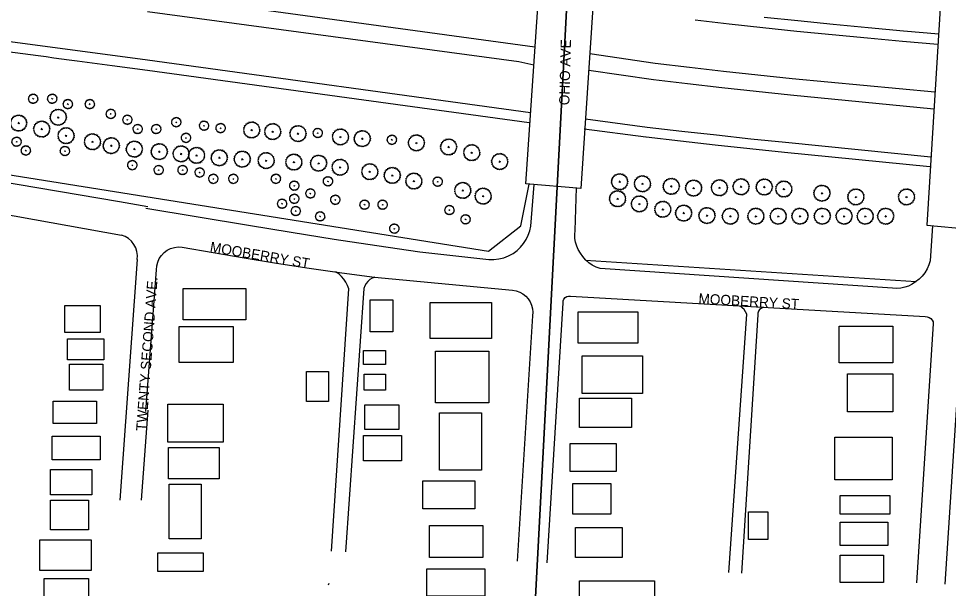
# Model space of a CAD drawing. Extents: x -9648 to 41057, y -12373 to 40276.
# Drawn here: x 11921 to 12833, y -5476 to -4917 of the extents above; entities that cross this region are included whole.
import ezdxf

# ---------------------------------------------------------------- set-up
doc = ezdxf.new("R2010")
doc.units = 0
for name, color, linetype in [('Default', 7, 'Continuous'), ('PM_X_Stop_Line', 7, 'Continuous'), ('SC_Scratch1', 7, 'Continuous'), ('SH_Data', 7, 'Continuous')]:
    doc.layers.add(name, color=color, linetype=linetype)

# ---------------------------------------------------------------- blocks, each defined once
blk = doc.blocks.new('15_PIN')
at = {"layer": 'Default'}
for p, q in [((-2.8, 0), (2.8, 0)), ((0, 2.8), (0, -2.8))]:
    blk.add_line(p, q, dxfattribs=at)
for centre, start, end in [((-25.5, 4.5), 275.99, 64.01), ((-25.9, -1.5), 289.3234, 77.3433), ((-23.8, 10.3), 262.6567, 50.6766), ((-20.8, 15.5), 249.3234, 37.3433), ((-16.7, 19.8), 235.99, 24.01), ((-11.6, 23.2), 222.6567, 10.6766), ((-6, 25.2), 209.3234, 357.3433), ((0, 25.9), 195.99, 344.01), ((6, 25.2), 182.6567, 330.6766), ((11.6, 23.2), 169.3234, 317.3433), ((16.7, 19.8), 155.99, 304.01), ((20.8, 15.5), 142.6567, 290.6766), ((23.8, 10.3), 129.3234, 277.3433), ((25.5, 4.5), 115.99, 264.01), ((25.9, -1.5), 102.6567, 250.6766), ((-24.8, -7.4), 302.6567, 90.6766), ((-22.4, -13), 315.99, 104.01), ((-18.8, -17.8), 329.3234, 117.3433), ((-14.2, -21.6), 342.6567, 130.6766), ((-8.9, -24.3), 355.99, 144.01), ((-3, -25.7), 9.3234, 157.3433), ((3, -25.7), 22.6567, 170.6766), ((8.9, -24.3), 35.99, 184.01), ((14.2, -21.6), 49.3234, 197.3433), ((18.8, -17.8), 62.6567, 210.6767), ((22.4, -13), 75.99, 224.01), ((24.8, -7.4), 89.3234, 237.3433)]:
    blk.add_arc(centre, 3.05, start, end, dxfattribs=at)

msp = doc.modelspace()

# ---------------------------------------------------------------- linework, layer by layer
at = {"layer": 'PM_X_Stop_Line'}
msp.add_arc((9361.23, -8468.95), 3904.03, 82.5, 82.5, dxfattribs=at)
at = {"layer": 'SC_Scratch1'}
for p, q in [((12492.94, -4255.51), (12411.7, -5793.36)), ((12411.7, -5793.36), (12492.94, -4255.51)), ((12492.94, -4255.51), (12411.7, -5793.36))]:
    msp.add_line(p, q, dxfattribs=at)
at = {"layer": 'SH_Data'}
for p, q in [((12418.48, -5079.16), (12435.28, -4831.86)), ((12488.68, -4838.26), (12472.68, -5083.66)), ((12826.88, -4875.06), (12811.88, -5119.86)), ((12427.58, -4944.96), (12047.69, -4893.08)), ((12047.7, -4910.08), (12411.88, -4959.26)), ((12584.68, -4918.26), (12617.98, -4922.06)), ((12617.98, -4922.06), (12651.18, -4925.76)), ((12685.52, -4919.32), (12652.22, -4915.82)), ((12719.98, -4922.81), (12685.48, -4919.31)), ((12754.53, -4926.11), (12719.93, -4922.81)), ((12651.18, -4925.76), (12684.48, -4929.26)), ((12684.48, -4929.26), (12718.98, -4932.76)), ((12718.98, -4932.76), (12753.58, -4936.06)), ((12789.1, -4929.3), (12754.5, -4926.1)), ((12823.64, -4932.3), (12789.04, -4929.3)), ((12753.58, -4936.06), (12788.18, -4939.26)), ((12788.18, -4939.26), (12822.78, -4942.26)), ((12481.28, -4951.36), (12545.48, -4960.86)), ((12481.28, -4951.36), (12545.48, -4960.86)), ((12423.18, -5009.46), (12047.73, -4957.68)), ((12411.88, -4959.26), (12426.38, -4962.46)), ((12421.85, -5019.37), (12047.73, -4967.88)), ((12480.28, -4967.66), (12543.68, -4976.86)), ((12545.48, -4960.86), (12578.98, -4964.86)), ((12545.48, -4960.86), (12578.98, -4964.86)), ((12578.98, -4964.86), (12612.58, -4968.66)), ((12578.98, -4964.86), (12612.58, -4968.66)), ((12612.58, -4968.66), (12646.08, -4972.36)), ((12612.58, -4968.66), (12646.08, -4972.36)), ((12543.68, -4976.86), (12577.28, -4980.86)), ((12646.08, -4972.36), (12679.68, -4975.86)), ((12679.68, -4975.86), (12819.88, -4989.06)), ((12577.28, -4980.86), (12610.88, -4984.66)), ((12610.88, -4984.66), (12644.48, -4988.36)), ((12644.48, -4988.36), (12678.08, -4991.86)), ((12678.08, -4991.86), (12818.88, -5005.56)), ((11514.42, -5006.69), (12381.93, -5145.2)), ((12477.08, -5015.56), (12537.68, -5023.46)), ((12537.68, -5023.46), (12571.58, -5027.46)), ((12536.38, -5033.38), (12475.78, -5025.48)), ((12570.4, -5037.39), (12536.5, -5033.39)), ((12571.58, -5027.46), (12605.48, -5031.26)), ((12605.48, -5031.26), (12639.38, -5034.96)), ((12604.36, -5041.2), (12570.46, -5037.4)), ((12638.29, -5044.9), (12604.39, -5041.2)), ((12639.38, -5034.96), (12673.28, -5038.46)), ((12673.28, -5038.46), (12815.98, -5052.66)), ((12672.25, -5048.41), (12638.35, -5044.91)), ((12814.99, -5062.61), (12672.29, -5048.41)), ((12472.68, -5083.66), (12418.48, -5079.16)), ((11785.61, -5087.23), (12022.03, -5129.49)), ((12413.71, -5120.39), (12421.77, -5079.44)), ((12423.48, -5120.66), (12426.68, -5079.86)), ((12466.88, -5125.06), (12468.28, -5083.26)), ((12046.08, -5103.06), (12146.68, -5119.66)), ((12146.68, -5119.66), (12188.58, -5126.66)), ((12381.93, -5145.2), (12413.71, -5120.39)), ((12422.48, -5125.26), (12423.48, -5120.66)), ((12811.88, -5119.86), (12864.68, -5124.66)), ((12817.48, -5120.36), (12815.08, -5154.66)), ((12188.58, -5126.66), (12230.58, -5133.46)), ((12230.58, -5133.46), (12272.58, -5139.86)), ((12416.38, -5137.76), (12418.88, -5133.86)), ((12418.88, -5133.86), (12420.88, -5129.66)), ((12420.88, -5129.66), (12422.48, -5125.26)), ((12466.58, -5128.86), (12466.88, -5125.06)), ((12466.78, -5132.76), (12466.58, -5128.86)), ((12467.48, -5136.56), (12466.78, -5132.76)), ((12066.98, -5144.36), (12070.28, -5142.66)), ((12070.28, -5142.66), (12073.98, -5141.56)), ((12073.98, -5141.56), (12077.68, -5141.06)), ((12077.68, -5141.06), (12081.48, -5141.26)), ((12081.48, -5141.26), (12142.28, -5151.66)), ((12272.58, -5139.86), (12314.68, -5146.06)), ((12410.08, -5144.66), (12413.48, -5141.36)), ((12413.48, -5141.36), (12416.38, -5137.76)), ((12468.58, -5140.26), (12467.48, -5136.56)), ((12470.08, -5143.76), (12468.58, -5140.26)), ((12059.18, -5152.56), (12061.28, -5149.36)), ((12061.28, -5149.36), (12063.88, -5146.66)), ((12063.88, -5146.66), (12066.98, -5144.36)), ((12142.28, -5151.66), (12174.18, -5156.96)), ((12314.68, -5146.06), (12382.48, -5153.46)), ((12392.28, -5152.86), (12397.08, -5151.66)), ((12397.08, -5151.66), (12401.68, -5149.86)), ((12401.68, -5149.86), (12406.08, -5147.56)), ((12406.08, -5147.56), (12410.08, -5144.66)), ((12472.08, -5147.06), (12470.08, -5143.76)), ((12474.38, -5150.56), (12472.08, -5147.06)), ((12477.08, -5153.86), (12474.38, -5150.56)), ((12037.45, -5153.49), (12020.35, -5389.45)), ((12037.45, -5153.49), (12020.35, -5389.45)), ((12056.48, -5163.46), (12056.78, -5159.66)), ((12056.78, -5159.66), (12057.68, -5155.96)), ((12057.68, -5155.96), (12059.18, -5152.56)), ((12174.18, -5156.96), (12206.18, -5161.86)), ((12382.48, -5153.46), (12387.38, -5153.46)), ((12387.38, -5153.46), (12392.28, -5152.86)), ((12480.28, -5156.66), (12477.08, -5153.86)), ((12477.2, -5153.97), (12801.34, -5175.1)), ((12483.68, -5158.96), (12480.28, -5156.66)), ((12487.48, -5160.86), (12483.68, -5158.96)), ((12491.48, -5162.26), (12487.48, -5160.86)), ((12813.88, -5158.76), (12812.08, -5162.66)), ((12815.08, -5154.66), (12813.88, -5158.76)), ((12046.08, -5302.66), (12056.48, -5163.46)), ((12206.18, -5161.86), (12238.18, -5166.46)), ((12235.08, -5167.66), (12232.08, -5165.56)), ((12237.68, -5170.06), (12235.08, -5167.66)), ((12240.08, -5172.76), (12237.68, -5170.06)), ((12238.18, -5166.46), (12270.28, -5170.66)), ((12778.28, -5181.46), (12491.48, -5162.26)), ((12807.28, -5169.76), (12804.28, -5172.86)), ((12809.88, -5166.36), (12807.28, -5169.76)), ((12812.08, -5162.66), (12809.88, -5166.36)), ((12242.18, -5175.66), (12240.08, -5172.76)), ((12243.78, -5178.86), (12242.18, -5175.66)), ((12245.08, -5182.26), (12243.78, -5178.86)), ((12260.68, -5179.36), (12259.88, -5181.86)), ((12261.98, -5176.96), (12260.68, -5179.36)), ((12263.68, -5174.86), (12261.98, -5176.96)), ((12265.58, -5173.06), (12263.68, -5174.86)), ((12267.88, -5171.66), (12265.58, -5173.06)), ((12270.38, -5170.66), (12267.88, -5171.66)), ((12270.28, -5170.66), (12405.68, -5183.66)), ((12793.98, -5179.46), (12790.18, -5180.66)), ((12797.58, -5177.66), (12793.98, -5179.46)), ((12800.88, -5175.46), (12797.58, -5177.66)), ((12804.28, -5172.86), (12800.88, -5175.46)), ((12227.97, -5439.5), (12245.08, -5182.26)), ((12259.88, -5181.86), (12241.65, -5440.24)), ((12405.68, -5183.66), (12409.18, -5184.26)), ((12409.18, -5184.26), (12412.58, -5185.46)), ((12412.58, -5185.46), (12415.68, -5187.16)), ((12415.68, -5187.16), (12418.48, -5189.36)), ((12782.28, -5181.76), (12778.28, -5181.46)), ((12786.28, -5181.46), (12782.28, -5181.76)), ((12790.18, -5180.66), (12786.28, -5181.46)), ((12418.48, -5189.36), (12420.88, -5192.06)), ((12420.88, -5192.06), (12422.78, -5195.06)), ((12422.78, -5195.06), (12424.18, -5198.26)), ((12439.62, -5450.98), (12455.08, -5195.86)), ((12455.08, -5195.86), (12455.18, -5193.96)), ((12455.18, -5193.96), (12455.88, -5192.26)), ((12455.88, -5192.26), (12457.18, -5190.76)), ((12457.18, -5190.76), (12458.78, -5189.76)), ((12458.78, -5189.76), (12460.58, -5189.36)), ((12460.58, -5189.36), (12462.48, -5189.46)), ((12462.48, -5189.46), (12810.28, -5209.46)), ((12424.18, -5198.26), (12425.08, -5201.76)), ((12425.08, -5201.76), (12425.38, -5205.26)), ((12425.38, -5205.26), (12425.08, -5208.86)), ((12630.88, -5200.76), (12628.88, -5199.06)), ((12632.68, -5202.66), (12630.88, -5200.76)), ((12634.18, -5204.76), (12632.68, -5202.66)), ((12635.48, -5207.06), (12634.18, -5204.76)), ((12646.88, -5204.16), (12646.28, -5205.96)), ((12646.28, -5205.96), (12646.28, -5207.86)), ((12647.88, -5202.56), (12646.88, -5204.16)), ((12649.38, -5201.36), (12647.88, -5202.56)), ((12651.68, -5200.36), (12649.38, -5201.36)), ((12425.08, -5208.86), (12410.19, -5449.38)), ((12617.68, -5460.65), (12635.48, -5207.06)), ((12646.28, -5207.86), (12630.13, -5461.32)), ((12810.28, -5209.46), (12812.28, -5209.56)), ((12812.28, -5209.56), (12814.18, -5210.26)), ((12814.18, -5210.26), (12815.78, -5211.36)), ((12815.78, -5211.36), (12817.08, -5212.86)), ((12817.08, -5212.86), (12817.98, -5214.66)), ((12817.98, -5214.66), (12818.28, -5216.66)), ((12818.28, -5216.66), (12801.77, -5470.64)), ((12829.88, -5472.16), (12846.28, -5220.46)), ((12225.18, -5472.66), (12225.88, -5471.06))]:
    msp.add_line(p, q, dxfattribs=at)
for points in [[(12047.73, -4957.68), (11819.52, -4927.41), (11700.8, -4912.08), (11582.1, -4896.74), (11446.2, -4878.61), (11310.28, -4860.69), (11087.86, -4831.62), (11024.6, -4823.65)], [(12047.81, -5101.68), (12020.01, -5096.9), (11026.11, -4928.25), (11019.91, -4926.86)], [(12047.73, -4967.88), (12013.05, -4963.29), (11978.54, -4958.92)], [(12047.92, -5301.28), (12041.36, -5389.44)], [(12047.92, -5301.28), (12041.36, -5389.44)]]:
    msp.add_lwpolyline(points, dxfattribs=at)
for points in [[(12082.56, -5181.83), (12143.95, -5181.83), (12143.95, -5212.53), (12082.56, -5212.53)], [(12266.08, -5192.93), (12288.29, -5192.93), (12288.29, -5224.29), (12266.08, -5224.29)], [(12324.86, -5195.55), (12384.95, -5195.55), (12384.95, -5230.83), (12324.86, -5230.83)], [(11966.61, -5198.69), (12001.08, -5198.69), (12001.08, -5225.22), (11966.61, -5225.22)], [(12469.85, -5204.69), (12528.63, -5204.69), (12528.63, -5235.4), (12469.85, -5235.4)], [(12078.64, -5219.07), (12131.54, -5219.07), (12131.54, -5254.35), (12078.64, -5254.35)], [(12725.77, -5218.73), (12778.42, -5218.73), (12778.42, -5254.83), (12725.77, -5254.83)], [(11969.26, -5231.41), (12004.62, -5231.41), (12004.62, -5251.74), (11969.26, -5251.74)], [(12259.55, -5242.59), (12281.11, -5242.59), (12281.11, -5256.31), (12259.55, -5256.31)], [(12330.09, -5243.24), (12382.34, -5243.24), (12382.34, -5294.2), (12330.09, -5294.2)], [(12473.77, -5247.81), (12533.21, -5247.81), (12533.21, -5285.05), (12473.77, -5285.05)], [(11971.03, -5256.16), (12003.73, -5256.16), (12003.73, -5281.8), (11971.03, -5281.8)], [(12203.39, -5263.49), (12224.94, -5263.49), (12224.94, -5292.89), (12203.39, -5292.89)], [(12260.21, -5266.11), (12281.11, -5266.11), (12281.11, -5281.78), (12260.21, -5281.78)], [(12734.06, -5265.48), (12778.42, -5265.48), (12778.42, -5302.76), (12734.06, -5302.76)], [(11955.12, -5292.41), (11997.55, -5292.41), (11997.55, -5314.52), (11955.12, -5314.52)], [(12067.54, -5295.5), (12121.75, -5295.5), (12121.75, -5332.74), (12067.54, -5332.74)], [(12260.86, -5296.16), (12294.17, -5296.16), (12294.17, -5320.33), (12260.86, -5320.33)], [(12471.16, -5289.62), (12522.1, -5289.62), (12522.1, -5318.37), (12471.16, -5318.37)], [(12334.01, -5304), (12375.15, -5304), (12375.15, -5360.18), (12334.01, -5360.18)], [(11954.23, -5326.9), (12001.08, -5326.9), (12001.08, -5349.89), (11954.23, -5349.89)], [(12259.55, -5326.21), (12296.78, -5326.21), (12296.78, -5351.04), (12259.55, -5351.04)], [(12462.02, -5334.05), (12507.08, -5334.05), (12507.08, -5361.49), (12462.02, -5361.49)], [(12721.63, -5327.61), (12777.83, -5327.61), (12777.83, -5369.63), (12721.63, -5369.63)], [(12068.19, -5337.97), (12117.83, -5337.97), (12117.83, -5368.68), (12068.19, -5368.68)], [(11952.47, -5359.61), (11993.13, -5359.61), (11993.13, -5384.37), (11952.47, -5384.37)], [(12317.68, -5370.64), (12368.62, -5370.64), (12368.62, -5398.08), (12317.68, -5398.08)], [(12068.84, -5373.9), (12100.19, -5373.9), (12100.19, -5427.48), (12068.84, -5427.48)], [(12464.63, -5373.25), (12501.86, -5373.25), (12501.86, -5403.3), (12464.63, -5403.3)], [(12726.96, -5385.01), (12775.47, -5385.01), (12775.47, -5403.35), (12726.96, -5403.35)], [(11952.47, -5389.67), (11989.59, -5389.67), (11989.59, -5418.85), (11952.47, -5418.85)], [(12637.04, -5400.99), (12655.97, -5400.99), (12655.97, -5428.21), (12637.04, -5428.21)], [(12324.21, -5414.41), (12376.46, -5414.41), (12376.46, -5445.77), (12324.21, -5445.77)], [(12467.24, -5416.37), (12512.96, -5416.37), (12512.96, -5445.77), (12467.24, -5445.77)], [(12726.96, -5411.05), (12773.69, -5411.05), (12773.69, -5434.13), (12726.96, -5434.13)], [(11941.86, -5428.58), (11992.24, -5428.58), (11992.24, -5458.64), (11941.86, -5458.64)], [(12057.74, -5441.2), (12102.15, -5441.2), (12102.15, -5459.49), (12057.74, -5459.49)], [(12726.96, -5443.59), (12769.55, -5443.59), (12769.55, -5470.22), (12726.96, -5470.22)], [(12321.6, -5456.88), (12378.42, -5456.88), (12378.42, -5483.66), (12321.6, -5483.66)], [(11946.28, -5466.6), (11989.59, -5466.6), (11989.59, -5495.78), (11946.28, -5495.78)], [(12471.16, -5468.64), (12544.96, -5468.64), (12544.96, -5516.33), (12471.16, -5516.33)]]:
    msp.add_lwpolyline(points, close=True, dxfattribs=at)
for centre, radius, start, end in [((10234.01, -17498.75), 12660.6, 82.080183, 83.191183), ((12016.18, -5150.21), 21.52, 351.24218, 74.23018), ((12016.18, -5150.21), 21.52, 351.24218, 74.23018)]:
    msp.add_arc(centre, radius, start, end, dxfattribs=at)

# ---------------------------------------------------------------- block references
for p, xscale, yscale, rotation in [((11935.46, -4995.71), 0.19138193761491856, 0.19138193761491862, 64.6147239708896), ((11954.14, -4995.71), 0.19138193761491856, 0.19138193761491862, 64.6147239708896), ((11969.46, -5000.98), 0.19138193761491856, 0.19138193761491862, 64.6147239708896), ((11991.01, -5000.98), 0.19138193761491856, 0.19138193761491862, 64.6147239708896), ((11960.05, -5013.87), 0.32808397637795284, 0.32808397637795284, 64.61472397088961), ((12011.61, -5010.56), 0.19138193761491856, 0.19138193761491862, 64.6147239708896), ((11921.17, -5019.62), 0.32808397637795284, 0.32808397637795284, 64.61472397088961), ((11943.84, -5025.47), 0.32808397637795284, 0.32808397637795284, 64.61472397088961), ((12027.89, -5016.31), 0.19138193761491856, 0.19138193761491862, 64.6147239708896), ((12075.78, -5018.71), 0.19138193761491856, 0.19138193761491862, 64.6147239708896), ((12149.82, -5026.34), 0.32808397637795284, 0.32808397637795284, 64.61472397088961), ((11967.73, -5031.95), 0.32808397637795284, 0.32808397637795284, 64.61472397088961), ((12037.95, -5025.41), 0.19138193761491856, 0.19138193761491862, 64.6147239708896), ((12056.15, -5025.41), 0.19138193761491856, 0.19138193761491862, 64.6147239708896), ((12103.04, -5022.11), 0.19138193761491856, 0.19138193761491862, 64.6147239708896), ((12119.31, -5024.5), 0.19138193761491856, 0.19138193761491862, 64.6147239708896), ((12170.42, -5027.95), 0.32808397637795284, 0.32808397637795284, 64.61472397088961), ((12195.23, -5029.9), 0.32808397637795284, 0.32808397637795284, 64.61472397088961), ((12214.53, -5029.29), 0.19138193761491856, 0.19138193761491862, 64.6147239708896), ((12236.83, -5033.16), 0.32808397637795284, 0.32808397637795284, 64.61472397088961), ((12258.26, -5034.84), 0.32808397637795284, 0.32808397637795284, 64.61472397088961), ((11919.17, -5037.87), 0.19138193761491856, 0.19138193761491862, 64.6147239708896), ((11993.61, -5037.91), 0.32808397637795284, 0.32808397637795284, 64.61472397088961), ((12012.08, -5041.7), 0.32808397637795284, 0.32808397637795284, 64.61472397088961), ((12085.33, -5034.07), 0.19138193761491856, 0.19138193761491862, 64.6147239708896), ((12287.26, -5035.99), 0.19138193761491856, 0.19138193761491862, 64.6147239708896), ((12311.31, -5038.98), 0.32808397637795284, 0.32808397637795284, 64.61472397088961), ((12342.97, -5043.06), 0.32808397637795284, 0.32808397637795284, 64.61472397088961), ((12342.97, -5043.06), 0.32808397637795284, 0.32808397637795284, 64.61472397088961), ((11928.27, -5046.49), 0.19138193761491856, 0.19138193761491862, 64.6147239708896), ((11966.59, -5046.97), 0.19138193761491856, 0.19138193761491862, 64.6147239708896), ((12034.68, -5045.15), 0.32808397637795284, 0.32808397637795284, 64.61472397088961), ((12059.17, -5047.62), 0.32808397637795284, 0.32808397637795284, 64.61472397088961), ((12080.51, -5049.76), 0.32808397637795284, 0.32808397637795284, 64.61472397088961), ((12095.68, -5051.27), 0.32808397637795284, 0.32808397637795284, 64.61472397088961), ((12117.99, -5053.65), 0.32808397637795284, 0.32808397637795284, 64.61472397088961), ((12365.61, -5048.62), 0.32808397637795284, 0.32808397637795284, 64.61472397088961), ((12140.49, -5054.98), 0.32808397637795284, 0.32808397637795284, 64.61472397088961), ((12163.94, -5056.36), 0.32808397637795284, 0.32808397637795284, 64.61472397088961), ((12191.1, -5057.84), 0.32808397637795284, 0.32808397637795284, 64.61472397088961), ((12215.38, -5058.94), 0.32808397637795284, 0.32808397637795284, 64.61472397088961), ((12236.5, -5062.92), 0.32808397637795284, 0.32808397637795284, 64.61472397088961), ((12393.03, -5057.33), 0.32808397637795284, 0.32808397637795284, 64.61472397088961), ((12032.68, -5060.87), 0.19138193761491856, 0.19138193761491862, 64.6147239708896), ((12058.54, -5065.66), 0.19138193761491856, 0.19138193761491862, 64.6147239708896), ((12082.01, -5065.66), 0.19138193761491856, 0.19138193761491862, 64.6147239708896), ((12265.61, -5067.29), 0.32808397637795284, 0.32808397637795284, 64.61472397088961), ((12287.61, -5070.93), 0.32808397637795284, 0.32808397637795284, 64.61472397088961), ((12098.73, -5068.06), 0.19138193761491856, 0.19138193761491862, 64.6147239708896), ((12112.13, -5074.28), 0.19138193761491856, 0.19138193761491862, 64.6147239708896), ((12131.75, -5074.28), 0.19138193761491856, 0.19138193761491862, 64.6147239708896), ((12173.49, -5074.28), 0.19138193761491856, 0.19138193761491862, 64.6147239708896), ((12308.8, -5076.47), 0.32808397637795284, 0.32808397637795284, 64.61472397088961), ((12510.64, -5077.16), 0.32808397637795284, 0.32808397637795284, 64.61472397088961), ((12533.01, -5079.16), 0.32808397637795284, 0.32808397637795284, 64.61472397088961), ((12191.56, -5080.98), 0.19138193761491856, 0.19138193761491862, 64.6147239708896), ((12224.58, -5076.68), 0.19138193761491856, 0.19138193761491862, 64.6147239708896), ((12332.15, -5077.04), 0.19138193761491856, 0.19138193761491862, 64.6147239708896), ((12356.76, -5085.68), 0.32808397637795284, 0.32808397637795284, 64.61472397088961), ((12561.26, -5081.68), 0.32808397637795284, 0.32808397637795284, 64.61472397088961), ((12583.14, -5083.41), 0.32808397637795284, 0.32808397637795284, 64.61472397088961), ((12608.47, -5083.07), 0.32808397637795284, 0.32808397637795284, 64.61472397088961), ((12629.71, -5082.11), 0.32808397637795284, 0.32808397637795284, 64.61472397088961), ((12652.52, -5082.33), 0.32808397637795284, 0.32808397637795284, 64.61472397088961), ((12671.67, -5084.29), 0.32808397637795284, 0.32808397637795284, 64.61472397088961), ((12709.07, -5088.39), 0.32808397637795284, 0.32808397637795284, 64.61472397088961), ((12191.56, -5093.91), 0.19138193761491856, 0.19138193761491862, 64.6147239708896), ((12207.35, -5088.64), 0.19138193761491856, 0.19138193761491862, 64.6147239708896), ((12376.76, -5091.26), 0.32808397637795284, 0.32808397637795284, 64.61472397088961), ((12508.58, -5093.84), 0.32808397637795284, 0.32808397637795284, 64.61472397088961), ((12530.02, -5098.86), 0.32808397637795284, 0.32808397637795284, 64.61472397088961), ((12742.32, -5092.03), 0.32808397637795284, 0.32808397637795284, 64.61472397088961), ((12791.97, -5092.03), 0.32808397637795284, 0.32808397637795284, 64.61472397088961), ((12179.6, -5098.69), 0.19138193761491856, 0.19138193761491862, 64.6147239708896), ((12231.75, -5094.86), 0.19138193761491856, 0.19138193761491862, 64.6147239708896), ((12260.46, -5099.65), 0.19138193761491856, 0.19138193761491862, 64.6147239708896), ((12278.17, -5099.65), 0.19138193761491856, 0.19138193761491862, 64.6147239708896), ((12552.99, -5104.21), 0.32808397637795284, 0.32808397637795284, 64.61472397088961), ((12573.41, -5107.95), 0.32808397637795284, 0.32808397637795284, 64.61472397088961), ((12193, -5105.87), 0.19138193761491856, 0.19138193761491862, 64.6147239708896), ((12216.92, -5111.14), 0.19138193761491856, 0.19138193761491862, 64.6147239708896), ((12343.72, -5104.92), 0.19138193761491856, 0.19138193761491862, 64.6147239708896), ((12596.29, -5110.31), 0.32808397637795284, 0.32808397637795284, 64.61472397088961), ((12619.21, -5110.93), 0.32808397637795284, 0.32808397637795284, 64.61472397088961), ((12644.2, -5110.93), 0.32808397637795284, 0.32808397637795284, 64.61472397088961), ((12666.14, -5110.93), 0.32808397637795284, 0.32808397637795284, 64.61472397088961), ((12687.47, -5110.93), 0.32808397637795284, 0.32808397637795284, 64.61472397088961), ((12709.41, -5110.93), 0.32808397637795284, 0.32808397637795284, 64.61472397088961), ((12730.74, -5110.93), 0.32808397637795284, 0.32808397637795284, 64.61472397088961), ((12751.46, -5110.93), 0.32808397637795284, 0.32808397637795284, 64.61472397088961), ((12771.57, -5110.93), 0.32808397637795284, 0.32808397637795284, 64.61472397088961), ((12359.51, -5114.01), 0.19138193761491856, 0.19138193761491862, 64.6147239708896), ((12289.65, -5123.1), 0.19138193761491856, 0.19138193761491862, 64.6147239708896)]:
    msp.add_blockref('15_PIN', p, dxfattribs=dict(at, xscale=xscale, yscale=yscale, rotation=rotation))

# ---------------------------------------------------------------- texts
at = {"layer": 'SC_Scratch1'}
for s, rotation, p in [('OHIO AVE', 88.50218, (12461.25, -5002.15)), ('MOOBERRY ST', 350.29344, (12108.26, -5145.77)), ('TWENTY SECOND AVE.', 85.74288, (12046.3, -5322.05)), ('MOOBERRY ST', 356.70887, (12587.73, -5196.59))]:
    msp.add_text(s, height=10, rotation=rotation, dxfattribs=at).set_placement(p)

doc.saveas('drawing.dxf')
